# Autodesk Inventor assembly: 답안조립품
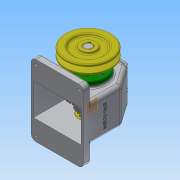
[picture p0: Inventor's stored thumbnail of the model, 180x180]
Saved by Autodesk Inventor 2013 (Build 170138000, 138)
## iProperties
Created: 2016-12
Part Number: 답안조립품
Document SubType Name: Assembly
Designer: Administrator
Author: Administrator
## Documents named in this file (15)
- C:\Users\Administrator\Desktop\461208V1015\답안조립품.iam
- C:\Users\Administrator\Desktop\461208V1015\본체.ipt
- C:\Users\Administrator\Desktop\461208V1015\V-벨트풀리.ipt
- C:\Users\Administrator\Desktop\461208V1015\뒤커버.ipt
- C:\Users\Administrator\Desktop\461208V1015\멈춤나사 - M4x10.ipt
- C:\Users\Administrator\Desktop\461208V1015\베어링 6203.ipt
- C:\Users\Administrator\Desktop\461208V1015\볼트 M3 x 8.ipt
- C:\Users\Administrator\Desktop\461208V1015\볼트 M3 x 10.ipt
- C:\Users\Administrator\Desktop\461208V1015\부시.ipt
- C:\Users\Administrator\Desktop\461208V1015\스퍼기어.ipt
- C:\Users\Administrator\Desktop\461208V1015\앞커버.ipt
- C:\Users\Administrator\Desktop\461208V1015\오일씰 28 40 8.ipt
- C:\Users\Administrator\Desktop\461208V1015\축.ipt
- C:\Users\Administrator\Desktop\461208V1015\키 - 5 x 5 x 18.ipt
- C:\Users\Administrator\Desktop\461208V1015\키 - 6 x 6 x 22.ipt
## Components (9 placed, 3 different names)
1. V-벨트풀리:1 — 플러쉬:1
2. ISO 4762 M3 x 8:1
3. ISO 4762 M3 x 8:2
4. ISO 4762 M3 x 8:3
5. ISO 4762 M3 x 8:4
6. ISO 4762 M3 x 10:1
7. ISO 4762 M3 x 10:2
8. ISO 4762 M3 x 10:3
9. ISO 4762 M3 x 10:4
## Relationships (1: Flush 1)
- 플러쉬:1 [Flush]: V-벨트풀리:1
